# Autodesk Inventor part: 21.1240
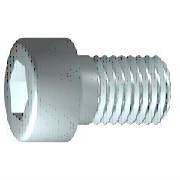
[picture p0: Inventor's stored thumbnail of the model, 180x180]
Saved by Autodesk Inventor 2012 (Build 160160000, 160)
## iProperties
Created: 2006-02
Part Number: 21.1240
Material: Steel, Mild
Description: M6x20 SHCS
Document SubType Name: Modeling
Standard: DIN 7984
Designer: Andy Moles
Standards Organization: DIN
Language: en-US
Size Designation: M6 x 20
Categories: <MemberInstance><Categories><Category DisplayName="Fasteners" InternalName="e4da775c-781d-43d5-af7c-5136215cf5a6" Mnemonic="FSTN"><Category DisplayName="Bolts"
Density: 7.86 g/cm^3
Vendor: S
Mass: 6.48581 g
Surface Area: 6.89561 cm^2
Volume: 0.825167 cm^3
Author: Andy Moles
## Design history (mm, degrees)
body "Solid1"
workplane "Work Plane1"
revolve "Body" stored, may be unused: angle "d10" = 90 deg
sketch "Sketch2"
  geometry: L1 (0, -6)-(0, 8) reference; L2 (-6, 0)-(8, 0) reference; L3 (2.309, 0)-(1.155, -2); L4 (1.155, -2)-(-1.155, -2); L5 (-1.155, -2)-(-2.309, 0); L6 (-2.309, 0)-(-1.155, 2); L7 (-1.155, 2)-(1.155, 2); L8 (1.155, 2)-(2.309, 0); 2 further points
  constraints: 12 end point, 1 coincident, 1 horizontal alignment, 1 point on line, 12 other
extrude "Slot" join sketch "Sketch2" stored distance "d11" = 10; taper "d12" = 0 deg
fillet "Fillet1" dims "d17" = 0.6 (= RR)
feature "Thread" dims "d13" = 20, "d14" = 0
chamfer "Chamfer1" distance "d15" = 0.61345 (= -0.5 x SPD + 0.5 x GD); stored, may be unused: second distance "d16" = 0.61345 (= GUL), angle "d27" = 45 deg
sketch "Sketch1"
  geometry: L1 (0.333, 0)-(20, 0); L2 (20, 0)-(20, 3); L3 (20, 3)-(3, 3); L4 (3, 3)-(2.386, 3); L5 (2.386, 3)-(0, 3); L6 (0, 3)-(0, 5); L7 (0, 5)-(-4, 5); L8 (-4, 5)-(-4, 2.309); L9 (-4, 2.309)-(-1, 2.309); L10 (-1, 2.309)-(0.333, 0); L11 (-6.4, 0)-(27.2, 0) reference; L12 (0, -0.5)-(0, 6.5) reference; L13 (3, 3)-(0, 3)
  constraints: 22 end point, 6 parallel, 2 collinear, 2 perpendicular, 1 horizontal, 1 midpoint
  dimensions: "d1" = 17 distance from line of L3.end L2 (= GEL); "d2" = 0.61355 distance of L4.end L3.end (computed from GAL); "d3" = 4 distance between parallel lines of L8 L6 (= KOH); "d4" = 3 distance of L8.end L9.end (= INTI); "d5" = 60 deg angle of L10 L1; "d6" = 6 diameter of L3 L1 (= GD); "d7" = 6 diameter of L5 L1 (= BDM); "d8" = 4.6188 diameter of L9 L1 (= 1.1547 x SW); "d9" = 10 diameter of L7 L1 (= KOD); "d26" = 20 distance between parallel lines of L12 L2 (= NLG)
other parameters: "GD" = 6 (= NND) [user parameter; used in 2 equation terms], "NLG" = 20 [user parameter; used in 1 equation term], "GEL" = 17 [user parameter; used in 1 equation term], "KOD" = 10 [user parameter; used in 1 equation term], "KOH" = 4 [user parameter; used in 1 equation term], "INTI" = 3 [user parameter; used in 1 equation term], "GAL" = 0.61345 (= 0.61345 x PTC) [user parameter; used in 1 equation term], "GUL" = 0.61345 (= 0.61345 x PTC) [user parameter; used in 1 equation term], "BDM" = 6 (= NND) [user parameter; used in 1 equation term], "SW" = 4 [user parameter; used in 2 equation terms], "RR" = 0.6 [user parameter; used in 1 equation term], "SPD" = 4.7731 (= NND - 1.2269 x PTC) [user parameter; used in 1 equation term], "d19" = 0, "d28" = 0, "d29" = 0, "TOA" = 30 deg [user parameter], "GD1" = 4.7731 (= THREADDIA - 1.2269 x PTC) [user parameter], "THREADDIA" = 6 [user parameter; used in 1 equation term], "FAWI" = 45 deg [user parameter], "ANG" = 120 deg [user parameter], "PTC" = 1 [user parameter; used in 5 equation terms], "NND" = 6 [user parameter; used in 3 equation terms], "E0" = 4.62 (= 1.155 x SW) [user parameter]
